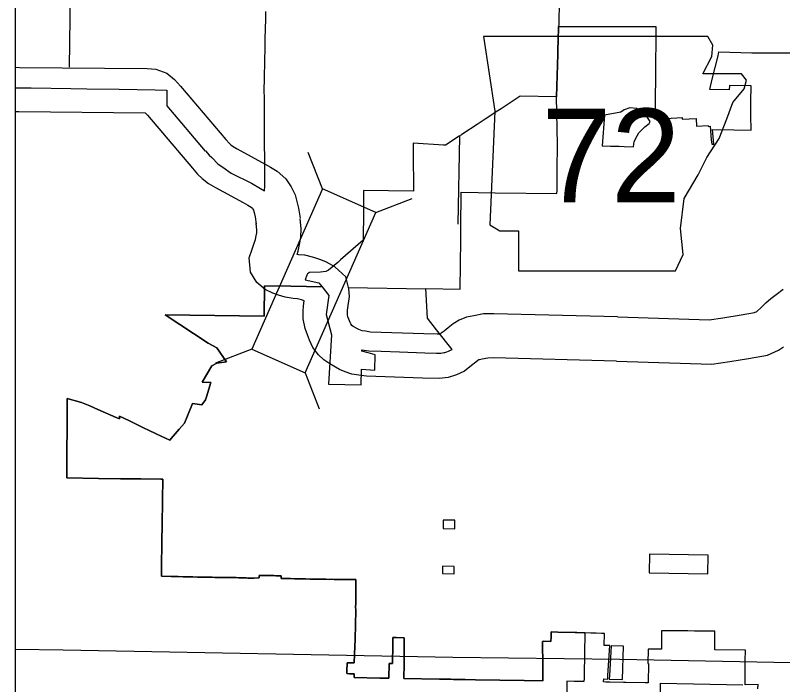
# Model space of a CAD drawing. Extents: x 309389.3 to 309420.2, y 336441.4 to 336461.2.
# Drawn here: x 309389.335 to 309390.124, y 336457.854 to 336458.542 of the extents above; entities that cross this region are included whole.
import ezdxf

# ---------------------------------------------------------------- set-up
doc = ezdxf.new("R2010")
doc.units = 0
for name, color, linetype in [('Level 24', 7, 'Continuous'), ('Level 37', 7, 'Continuous'), ('Level 4', 7, 'Continuous'), ('Level 62', 7, 'Continuous'), ('R_Contours', 7, 'Continuous'), ('R_MOT', 7, 'Continuous')]:
    doc.layers.add(name, color=color, linetype=linetype)

msp = doc.modelspace()

# ---------------------------------------------------------------- linework, layer by layer
at = {"layer": 'Level 24'}
for points in [[(309389.33514, 336458.48856), (309389.33946, 336458.48847), (309389.4708, 336458.48723), (309389.47977, 336458.48674), (309389.49099, 336458.48255), (309389.49889, 336458.47603), (309389.5051, 336458.46911), (309389.55175, 336458.41429), (309389.55535, 336458.41011), (309389.55665, 336458.40889), (309389.55919, 336458.40696), (309389.56328, 336458.40455), (309389.59207, 336458.38905), (309389.59749, 336458.3858), (309389.60453, 336458.38162), (309389.61336, 336458.37394), (309389.61896, 336458.36563), (309389.62294, 336458.35752), (309389.62479, 336458.35049), (309389.62651, 336458.34359), (309389.62794, 336458.33348)], [(309389.33514, 336458.4431), (309389.33878, 336458.44302), (309389.46854, 336458.4418), (309389.47088, 336458.43919), (309389.51722, 336458.38473), (309389.52246, 336458.37864), (309389.52725, 336458.37414), (309389.53384, 336458.36914), (309389.54098, 336458.36494), (309389.5696, 336458.34953), (309389.57421, 336458.34676), (309389.5778, 336458.34463), (309389.57901, 336458.34358), (309389.57952, 336458.34282), (309389.58014, 336458.34156), (309389.58076, 336458.3392), (309389.58184, 336458.33489), (309389.58293, 336458.32712)], [(309389.95453, 336458.23188), (309389.82708, 336458.23519), (309389.81643, 336458.23496), (309389.80665, 336458.23319), (309389.79914, 336458.23161), (309389.79164, 336458.22851), (309389.78544, 336458.22485), (309389.78023, 336458.22085), (309389.77599, 336458.21732), (309389.77313, 336458.21511), (309389.77231, 336458.21472), (309389.77088, 336458.21428), (309389.7691, 336458.21408), (309389.75507, 336458.21443), (309389.70049, 336458.21628), (309389.69516, 336458.21713), (309389.69192, 336458.21758), (309389.69025, 336458.21817), (309389.68838, 336458.21891), (309389.68264, 336458.2222), (309389.68132, 336458.22309), (309389.68117, 336458.22324), (309389.68001, 336458.22475), (309389.67933, 336458.22615), (309389.67804, 336458.2295), (309389.67711, 336458.23202), (309389.67673, 336458.23415), (309389.67672, 336458.23634), (309389.6769, 336458.23889), (309389.67875, 336458.25279), (309389.67805, 336458.26085), (309389.67485, 336458.27301), (309389.66381, 336458.28359), (309389.65513, 336458.28815), (309389.64932, 336458.29071), (309389.642, 336458.29312), (309389.6327, 336458.29541), (309389.62648, 336458.29591), (309389.62485, 336458.2962), (309389.62591, 336458.29952), (309389.62745, 336458.30622), (309389.62869, 336458.31342), (309389.62911, 336458.32279), (309389.62803, 336458.33274)], [(309389.95335, 336458.18644), (309389.82699, 336458.18973), (309389.82101, 336458.18959), (309389.81538, 336458.18857), (309389.81262, 336458.18799), (309389.81197, 336458.18773), (309389.81093, 336458.18711), (309389.80861, 336458.18533), (309389.80441, 336458.18184), (309389.79702, 336458.17613), (309389.7888, 336458.17224), (309389.78026, 336458.16961), (309389.77115, 336458.16856), (309389.75374, 336458.16899), (309389.69613, 336458.17095), (309389.68845, 336458.17217), (309389.6811, 336458.17319), (309389.67429, 336458.1756), (309389.6686, 336458.17786), (309389.65858, 336458.1836), (309389.65231, 336458.18783), (309389.647, 336458.19312), (309389.64117, 336458.20067), (309389.63759, 336458.20804), (309389.63551, 336458.21347), (309389.63308, 336458.22003), (309389.63129, 336458.23002), (309389.63126, 336458.23783), (309389.63165, 336458.24347), (309389.63232, 336458.24845), (309389.62942, 336458.24941), (309389.62541, 336458.2504), (309389.62073, 336458.25077), (309389.61246, 336458.25222), (309389.60577, 336458.25423), (309389.59985, 336458.25626), (309389.59209, 336458.26025), (309389.58358, 336458.2673), (309389.57714, 336458.27796), (309389.57561, 336458.29264), (309389.57875, 336458.30156), (309389.58044, 336458.30657), (309389.58204, 336458.31156), (309389.58287, 336458.31518), (309389.58341, 336458.3183), (309389.58354, 336458.32135), (309389.58284, 336458.32786)], [(309389.95462, 336458.23188), (309390.04875, 336458.22904), (309390.06287, 336458.2311), (309390.08151, 336458.2342), (309390.09536, 336458.23654), (309390.09784, 336458.23766), (309390.09854, 336458.23825), (309390.10136, 336458.2411), (309390.10682, 336458.24647), (309390.11209, 336458.25103), (309390.11766, 336458.25514), (309390.12472, 336458.26047)], [(309389.95325, 336458.18645), (309390.05135, 336458.18349), (309390.06988, 336458.18618), (309390.08903, 336458.18937), (309390.10874, 336458.1927), (309390.11983, 336458.19772), (309390.12497, 336458.2011)], [(309389.95668, 336457.87989), (309389.78498, 336457.88189), (309389.38426, 336457.88925), (309389.33514, 336457.89017)], [(309390.73336, 336457.86577), (309390.58465, 336457.86645), (309390.18588, 336457.87537), (309389.95686, 336457.87988)]]:
    msp.add_lwpolyline(points, dxfattribs=at)
at = {"layer": 'Level 37'}
for p, q in [((309389.65088, 336458.36354), (309389.63641, 336458.40083)), ((309389.70578, 336458.33934), (309389.74307, 336458.35381)), ((309389.57828, 336458.19883), (309389.54099, 336458.18436)), ((309389.63318, 336458.17463), (309389.64765, 336458.13734))]:
    msp.add_line(p, q, dxfattribs=at)
msp.add_lwpolyline([(309389.63318, 336458.17463), (309389.70578, 336458.33934), (309389.65088, 336458.36354), (309389.57828, 336458.19883)], close=True, dxfattribs=at)
at = {"layer": 'Level 4'}
for points in [[(309389.3909, 336458.48864), (309389.39318, 336458.66533), (309389.3932, 336458.66655)], [(309389.79193, 336458.41787), (309389.79031, 336458.32724)], [(309389.75737, 336458.26031), (309389.67727, 336458.26172)]]:
    msp.add_lwpolyline(points, dxfattribs=at)
at = {"layer": 'Level 62'}
for points in [[(309389.89457, 336458.5567), (309389.89391, 336458.53278), (309389.89384, 336458.53045)], [(309389.33514, 336458.46749), (309389.34942, 336458.46731), (309389.35135, 336458.46729), (309389.3922, 336458.46679), (309389.40867, 336458.4665), (309389.44177, 336458.4659), (309389.47878, 336458.46523), (309389.49097, 336458.46501), (309389.49093, 336458.45832), (309389.49088, 336458.44875), (309389.53028, 336458.40237), (309389.53057, 336458.40261), (309389.53443, 336458.39813), (309389.53714, 336458.39571), (309389.54385, 336458.38897), (309389.54866, 336458.38583), (309389.55725, 336458.37982), (309389.57801, 336458.36936), (309389.58715, 336458.36407), (309389.59128, 336458.36154), (309389.5918, 336458.36633), (309389.59163, 336458.39375), (309389.59152, 336458.41045), (309389.5915, 336458.41429), (309389.59138, 336458.43265), (309389.59131, 336458.44463), (309389.59124, 336458.45569), (309389.59122, 336458.45857), (309389.59119, 336458.46315), (309389.59148, 336458.47873), (309389.59176, 336458.49365), (309389.59209, 336458.51031), (309389.59216, 336458.51409), (309389.59223, 336458.51767), (309389.59262, 336458.53789), (309389.59277, 336458.54578)], [(309389.89384, 336458.53045), (309389.89342, 336458.51547), (309389.8932, 336458.5076), (309389.89305, 336458.502), (309389.89183, 336458.45829), (309389.8544, 336458.45878), (309389.83487, 336458.44599), (309389.83122, 336458.4436), (309389.81834, 336458.43517), (309389.81016, 336458.42981), (309389.79536, 336458.42012), (309389.79399, 336458.41923), (309389.79163, 336458.41768), (309389.77762, 336458.40851), (309389.77538, 336458.40865), (309389.74436, 336458.41048), (309389.74439, 336458.40168), (309389.74448, 336458.36106), (309389.69334, 336458.36197), (309389.69319, 336458.34071), (309389.69297, 336458.31091), (309389.66952, 336458.29051), (309389.66668, 336458.28804), (309389.65724, 336458.27983), (309389.65432, 336458.27875), (309389.64893, 336458.27795), (309389.63773, 336458.2775), (309389.63569, 336458.27638), (309389.63506, 336458.27472), (309389.63331, 336458.27017), (309389.63335, 336458.27016), (309389.64718, 336458.26709), (309389.65069, 336458.26294), (309389.61845, 336458.26342), (309389.59142, 336458.26383), (309389.59095, 336458.23275), (309389.48936, 336458.23412), (309389.53337, 336458.20479), (309389.54234, 336458.20007), (309389.5522, 336458.1857), (309389.54221, 336458.18432), (309389.53727, 336458.18183), (309389.52733, 336458.16474), (309389.53628, 336458.1646), (309389.53161, 336458.14995), (309389.53062, 336458.14683), (309389.52685, 336458.14149), (309389.51738, 336458.14296), (309389.51669, 336458.14133), (309389.51206, 336458.13027), (309389.50895, 336458.12286), (309389.50356, 336458.11671), (309389.49538, 336458.107), (309389.49395, 336458.10533), (309389.48048, 336458.11149), (309389.47707, 336458.11314), (309389.47494, 336458.11417), (309389.46502, 336458.11898), (309389.4524, 336458.12509), (309389.44213, 336458.13006), (309389.44224, 336458.12711), (309389.43871, 336458.12869), (309389.41998, 336458.13685), (309389.41634, 336458.13841), (309389.41538, 336458.13882), (309389.41167, 336458.14041), (309389.40306, 336458.14398), (309389.38853, 336458.14807), (309389.38835, 336458.11827), (309389.3882, 336458.09334), (309389.38804, 336458.06641), (309389.42069, 336458.06598), (309389.44338, 336458.06567), (309389.46429, 336458.06539), (309389.48469, 336458.06511), (309389.4868, 336458.06508), (309389.48668, 336458.05696), (309389.4866, 336458.05216), (309389.48653, 336458.04737), (309389.48646, 336458.04258), (309389.48639, 336458.03784), (309389.48631, 336458.03305), (309389.48624, 336458.02824), (309389.48617, 336458.02346), (309389.4861, 336458.01869), (309389.48605, 336458.01543), (309389.48602, 336458.01395), (309389.48597, 336458.01039), (309389.48595, 336458.00916), (309389.48588, 336458.00441), (309389.48581, 336457.9996), (309389.48573, 336457.99478), (309389.48566, 336457.99001), (309389.48559, 336457.98525), (309389.48552, 336457.98072), (309389.48549, 336457.97855), (309389.48539, 336457.97246), (309389.48533, 336457.96546), (309389.49551, 336457.9652), (309389.50255, 336457.96503)], [(309389.89251, 336458.39023), (309389.89263, 336458.40189), (309389.89271, 336458.40919), (309389.89183, 336458.45829), (309389.89305, 336458.502), (309389.8932, 336458.5076), (309389.89342, 336458.51547), (309389.89384, 336458.53045), (309389.91649, 336458.53048), (309389.93203, 336458.53052), (309389.994, 336458.53058), (309389.99369, 336458.50607), (309389.99364, 336458.50209), (309389.99353, 336458.49309), (309389.99334, 336458.47786), (309389.99308, 336458.45679), (309389.99298, 336458.44622), (309389.99296, 336458.44463), (309389.99287, 336458.43511), (309390.02086, 336458.43701), (309390.02098, 336458.43512), (309390.03523, 336458.43606), (309390.03573, 336458.4279), (309390.04779, 336458.42871), (309390.04787, 336458.42781), (309390.04966, 336458.42793), (309390.05091, 336458.41395), (309390.05129, 336458.40966), (309390.0535, 336458.40966), (309390.05225, 336458.42449), (309390.0742, 336458.4241), (309390.09185, 336458.42379), (309390.09162, 336458.43897), (309390.09139, 336458.45347), (309390.09176, 336458.46939), (309390.06952, 336458.46978), (309390.06908, 336458.46536), (309390.0493, 336458.46587), (309390.05182, 336458.47622), (309390.05777, 336458.50038), (309390.05862, 336458.50438), (309390.09257, 336458.50346), (309390.11997, 336458.50331), (309390.14346, 336458.50322)], [(309389.48588, 336458.00441), (309389.48595, 336458.00916), (309389.48597, 336458.01039), (309389.48602, 336458.01395), (309389.48605, 336458.01543), (309389.4861, 336458.01869), (309389.48617, 336458.02346), (309389.48624, 336458.02824), (309389.48631, 336458.03305), (309389.48639, 336458.03784), (309389.48646, 336458.04258), (309389.48653, 336458.04737), (309389.4866, 336458.05216), (309389.48668, 336458.05696), (309389.4868, 336458.06508), (309389.48469, 336458.06511), (309389.46429, 336458.06539), (309389.44338, 336458.06567), (309389.42069, 336458.06598), (309389.38804, 336458.06641), (309389.3882, 336458.09334), (309389.38835, 336458.11827), (309389.38853, 336458.14807), (309389.40306, 336458.14398), (309389.41167, 336458.14041), (309389.41538, 336458.13882), (309389.41634, 336458.13841), (309389.41998, 336458.13685), (309389.43871, 336458.12869), (309389.44224, 336458.12711), (309389.44213, 336458.13006), (309389.4524, 336458.12509), (309389.46502, 336458.11898), (309389.47494, 336458.11417), (309389.47707, 336458.11314), (309389.48048, 336458.11149), (309389.49395, 336458.10533), (309389.49538, 336458.107), (309389.50356, 336458.11671), (309389.50895, 336458.12286), (309389.51206, 336458.13027), (309389.51669, 336458.14133), (309389.51738, 336458.14296), (309389.52685, 336458.14149), (309389.53062, 336458.14683), (309389.53161, 336458.14995), (309389.53628, 336458.1646), (309389.52733, 336458.16474), (309389.53727, 336458.18183), (309389.54221, 336458.18432), (309389.5522, 336458.1857), (309389.54234, 336458.20007), (309389.53337, 336458.20479), (309389.48936, 336458.23412), (309389.59095, 336458.23275), (309389.59142, 336458.26383), (309389.61845, 336458.26342), (309389.65069, 336458.26294), (309389.65765, 336458.25387), (309389.65488, 336458.23447), (309389.66042, 336458.21345), (309389.6571, 336458.16278), (309389.69074, 336458.16227), (309389.69104, 336458.17817), (309389.70479, 336458.17728), (309389.70534, 336458.19281), (309389.69784, 336458.19486), (309389.69139, 336458.19662), (309389.69142, 336458.19824), (309389.69876, 336458.19723), (309389.71128, 336458.19676), (309389.73037, 336458.196), (309389.75612, 336458.19503), (309389.76839, 336458.19457), (309389.76926, 336458.19455), (309389.77037, 336458.19456), (309389.77153, 336458.19462), (309389.77286, 336458.19474), (309389.77431, 336458.19494), (309389.77573, 336458.19521), (309389.77688, 336458.19548), (309389.77889, 336458.19607), (309389.78076, 336458.19676), (309389.78267, 336458.19763), (309389.78433, 336458.19851), (309389.78436, 336458.19853), (309389.76841, 336458.21877), (309389.75913, 336458.23055), (309389.75732, 336458.26117), (309389.79277, 336458.26056), (309389.79321, 336458.3112), (309389.79331, 336458.32355), (309389.79363, 336458.36018), (309389.82843, 336458.35965), (309389.89216, 336458.35869), (309389.8922, 336458.36182), (309389.89229, 336458.36977), (309389.89236, 336458.37659), (309389.89243, 336458.38341), (309389.89251, 336458.39023)], [(309389.68373, 336457.86127), (309389.68375, 336457.86508), (309389.68375, 336457.86515), (309389.67867, 336457.86523), (309389.67604, 336457.86528), (309389.67611, 336457.86796), (309389.67633, 336457.8763), (309389.68369, 336457.87633), (309389.6843, 336457.89348), (309389.68446, 336457.89987), (309389.68461, 336457.9028), (309389.68471, 336457.90543), (309389.68492, 336457.91098), (309389.68513, 336457.91649), (309389.68513, 336457.92182), (309389.68514, 336457.92407), (309389.68515, 336457.92723), (309389.68514, 336457.93165), (309389.68513, 336457.93285), (309389.68516, 336457.93806), (309389.68515, 336457.93922), (309389.68514, 336457.94367), (309389.68515, 336457.94681), (309389.68516, 336457.94915), (309389.68514, 336457.95439), (309389.68516, 336457.95691), (309389.68514, 336457.96193), (309389.68286, 336457.96197), (309389.67791, 336457.96203), (309389.67672, 336457.96206), (309389.67302, 336457.9621), (309389.67052, 336457.96208), (309389.66802, 336457.96211), (309389.66516, 336457.96215), (309389.66313, 336457.9622), (309389.65981, 336457.96221), (309389.6583, 336457.96213), (309389.65444, 336457.96226), (309389.65329, 336457.96226), (309389.6491, 336457.96234), (309389.64846, 336457.96236), (309389.64373, 336457.96245), (309389.64352, 336457.96245), (309389.6386, 336457.96255), (309389.63836, 336457.96255), (309389.63367, 336457.96264), (309389.63301, 336457.96265), (309389.6286, 336457.96274), (309389.62763, 336457.96276), (309389.62335, 336457.96284), (309389.62228, 336457.96286), (309389.61808, 336457.96294), (309389.61691, 336457.96296), (309389.61314, 336457.96303), (309389.61153, 336457.96307), (309389.60844, 336457.96313), (309389.60844, 336457.96589), (309389.60622, 336457.96592), (309389.60292, 336457.96596), (309389.60085, 336457.96598), (309389.5979, 336457.96601), (309389.5934, 336457.96606), (309389.59119, 336457.9661), (309389.58575, 336457.96618), (309389.58575, 336457.96361), (309389.58082, 336457.96354), (309389.57438, 336457.96357), (309389.57235, 336457.96368), (309389.57072, 336457.96373), (309389.56734, 336457.96384), (309389.56465, 336457.96389), (309389.56233, 336457.96394), (309389.55887, 336457.96402), (309389.55736, 336457.96401), (309389.55253, 336457.96399), (309389.54746, 336457.96413), (309389.54649, 336457.96415), (309389.54245, 336457.96421), (309389.54045, 336457.96423), (309389.53747, 336457.96431), (309389.53438, 336457.96439), (309389.53243, 336457.96442), (309389.52775, 336457.9645), (309389.52742, 336457.96449), (309389.52513, 336457.96445), (309389.52252, 336457.96452), (309389.51763, 336457.96464), (309389.5125, 336457.96477), (309389.50757, 336457.9649), (309389.50255, 336457.96503), (309389.49551, 336457.9652), (309389.48533, 336457.96546), (309389.48539, 336457.97246), (309389.48549, 336457.97855), (309389.48552, 336457.98072), (309389.48559, 336457.98525), (309389.48566, 336457.99001), (309389.48573, 336457.99478), (309389.48581, 336457.9996), (309389.48588, 336458.00441)], [(309389.50255, 336457.96503), (309389.50757, 336457.9649), (309389.5125, 336457.96477), (309389.51763, 336457.96464), (309389.52252, 336457.96452), (309389.52513, 336457.96445), (309389.52742, 336457.96449), (309389.52775, 336457.9645), (309389.53243, 336457.96442), (309389.53438, 336457.96439), (309389.53747, 336457.96431), (309389.54045, 336457.96423), (309389.54245, 336457.96421), (309389.54649, 336457.96415), (309389.54746, 336457.96413), (309389.55253, 336457.96399), (309389.55736, 336457.96401), (309389.55887, 336457.96402), (309389.56233, 336457.96394), (309389.56465, 336457.96389), (309389.56734, 336457.96384), (309389.57072, 336457.96373), (309389.57235, 336457.96368), (309389.57438, 336457.96357), (309389.58082, 336457.96354), (309389.58575, 336457.96361), (309389.58575, 336457.96618), (309389.59119, 336457.9661), (309389.5934, 336457.96606), (309389.5979, 336457.96601), (309389.60085, 336457.96598), (309389.60292, 336457.96596), (309389.60622, 336457.96592), (309389.60844, 336457.96589), (309389.60844, 336457.96313), (309389.61153, 336457.96307), (309389.61314, 336457.96303), (309389.61691, 336457.96296), (309389.61808, 336457.96294), (309389.62228, 336457.96286), (309389.62335, 336457.96284), (309389.62763, 336457.96276), (309389.6286, 336457.96274), (309389.63301, 336457.96265), (309389.63367, 336457.96264), (309389.63836, 336457.96255), (309389.6386, 336457.96255), (309389.64352, 336457.96245), (309389.64373, 336457.96245), (309389.64846, 336457.96236), (309389.6491, 336457.96234), (309389.65329, 336457.96226), (309389.65444, 336457.96226), (309389.6583, 336457.96213), (309389.65981, 336457.96221), (309389.66313, 336457.9622), (309389.66516, 336457.96215), (309389.66802, 336457.96211), (309389.67052, 336457.96208), (309389.67302, 336457.9621), (309389.67672, 336457.96206), (309389.67791, 336457.96203), (309389.68286, 336457.96197), (309389.68514, 336457.96193), (309389.68516, 336457.95691), (309389.68514, 336457.95439), (309389.68516, 336457.94915), (309389.68515, 336457.94681), (309389.68514, 336457.94367), (309389.68515, 336457.93922), (309389.68516, 336457.93806), (309389.68513, 336457.93285), (309389.68514, 336457.93165), (309389.68515, 336457.92723), (309389.68514, 336457.92407), (309389.68513, 336457.92182), (309389.68513, 336457.91649), (309389.68492, 336457.91098), (309389.68471, 336457.90543), (309389.68461, 336457.9028), (309389.68446, 336457.89987), (309389.6843, 336457.89348), (309389.68369, 336457.87633), (309389.67633, 336457.8763), (309389.67611, 336457.86796), (309389.67604, 336457.86528), (309389.67867, 336457.86523), (309389.68375, 336457.86515), (309389.68375, 336457.86508), (309389.68373, 336457.86127), (309389.70994, 336457.86078), (309389.71936, 336457.86061), (309389.71943, 336457.87559), (309389.72314, 336457.87553), (309389.72317, 336457.88148), (309389.72323, 336457.88906), (309389.72334, 336457.90231), (309389.7267, 336457.90229), (309389.72672, 336457.90229), (309389.73428, 336457.90212)], [(309390.09888, 336457.8496), (309390.09895, 336457.85415), (309390.08576, 336457.85378), (309390.0858, 336457.85741), (309390.08581, 336457.85794), (309390.08585, 336457.86093), (309390.0857, 336457.87855), (309390.08594, 336457.88923), (309390.05465, 336457.88969), (309390.05459, 336457.90889), (309390.05028, 336457.90893), (309390.04475, 336457.90897), (309390.0415, 336457.909), (309390.03922, 336457.90901), (309390.03369, 336457.90906), (309390.02683, 336457.90911), (309390.02368, 336457.90915), (309390.01178, 336457.90923), (309389.99975, 336457.90923), (309389.99954, 336457.89034), (309389.99017, 336457.89041), (309389.98668, 336457.89044), (309389.98597, 336457.89045), (309389.9857, 336457.87579), (309389.98641, 336457.87577), (309389.98603, 336457.85574), (309389.98281, 336457.85582), (309389.96314, 336457.85623), (309389.96236, 336457.85624), (309389.9605, 336457.85628), (309389.94664, 336457.85656), (309389.94488, 336457.8566), (309389.94249, 336457.85665), (309389.94007, 336457.8567), (309389.94021, 336457.85982), (309389.94442, 336457.85962), (309389.94463, 336457.86347), (309389.94636, 336457.89405), (309389.94071, 336457.89425), (309389.94104, 336457.9066), (309389.94064, 336457.90661), (309389.93782, 336457.90669), (309389.93233, 336457.90686), (309389.93072, 336457.90691), (309389.92684, 336457.90702), (309389.92079, 336457.9072), (309389.9203, 336457.90721), (309389.91273, 336457.90743), (309389.91077, 336457.90749), (309389.89297, 336457.90805), (309389.88628, 336457.90826), (309389.8861, 336457.90326), (309389.88601, 336457.89848), (309389.87868, 336457.89859), (309389.87738, 336457.89843), (309389.87735, 336457.89237), (309389.87736, 336457.89161), (309389.87746, 336457.87986), (309389.87767, 336457.85791), (309389.85826, 336457.85822), (309389.8084, 336457.85903), (309389.79781, 336457.8592), (309389.7858, 336457.8594), (309389.78308, 336457.85944), (309389.7715, 336457.85965), (309389.73479, 336457.86032), (309389.73486, 336457.87537), (309389.7349, 336457.88042), (309389.7349, 336457.88042), (309389.73495, 336457.88854), (309389.73495, 336457.88878), (309389.735, 336457.89492), (309389.73506, 336457.9021), (309389.73428, 336457.90212), (309389.72672, 336457.90229), (309389.7267, 336457.90229), (309389.72334, 336457.90231), (309389.72323, 336457.88906), (309389.72317, 336457.88148), (309389.72314, 336457.87553), (309389.71943, 336457.87559), (309389.71936, 336457.86061), (309389.70994, 336457.86078), (309389.68373, 336457.86127)], [(309389.73428, 336457.90212), (309389.73506, 336457.9021), (309389.735, 336457.89492), (309389.73495, 336457.88878), (309389.73495, 336457.88854), (309389.7349, 336457.88042), (309389.7349, 336457.88042), (309389.73486, 336457.87537), (309389.73479, 336457.86032), (309389.7715, 336457.85965), (309389.78308, 336457.85944), (309389.7858, 336457.8594), (309389.79781, 336457.8592), (309389.8084, 336457.85903), (309389.85826, 336457.85822), (309389.87767, 336457.85791), (309389.87746, 336457.87986), (309389.87736, 336457.89161), (309389.87735, 336457.89237), (309389.87738, 336457.89843), (309389.87868, 336457.89859), (309389.88601, 336457.89848), (309389.8861, 336457.90326), (309389.88628, 336457.90826), (309389.89297, 336457.90805), (309389.91077, 336457.90749), (309389.91273, 336457.90743), (309389.9203, 336457.90721), (309389.92079, 336457.9072), (309389.92003, 336457.86403), (309389.91996, 336457.86022), (309389.91991, 336457.85711), (309389.90987, 336457.85732), (309389.90217, 336457.85748), (309389.90198, 336457.83135)], [(309389.9986, 336457.80763), (309389.99869, 336457.85549), (309390.08315, 336457.85383)]]:
    msp.add_lwpolyline(points, dxfattribs=at)
for points in [[(309389.97094, 336458.4069), (309389.97161, 336458.41219), (309389.97457, 336458.4182), (309389.97619, 336458.4213), (309389.9787, 336458.42357), (309389.9824, 336458.4274), (309389.98688, 336458.43064), (309389.98807, 336458.43285), (309389.98206, 336458.44165), (309389.97444, 336458.44616), (309389.96698, 336458.44684), (309389.9614, 336458.44484), (309389.95771, 336458.44233), (309389.94088, 336458.43918), (309389.93858, 336458.40784), (309389.94737, 336458.40759), (309389.95614, 336458.40733), (309389.96117, 336458.40718)], [(309389.787, 336458.0141), (309389.78705, 336458.01831), (309389.78711, 336458.02287), (309389.77516, 336458.0231), (309389.77513, 336458.02134), (309389.77509, 336458.01853), (309389.77502, 336458.01435)], [(309390.04719, 336457.96801), (309390.04769, 336457.98698), (309389.98723, 336457.988), (309389.98698, 336457.96892)], [(309389.78641, 336457.96774), (309389.78648, 336457.97319), (309389.78651, 336457.9754), (309389.77443, 336457.97566), (309389.77432, 336457.9685), (309389.77431, 336457.96806)], [(309389.95972, 336457.85933), (309389.9607, 336457.89352), (309389.94787, 336457.89399), (309389.94615, 336457.86343), (309389.94593, 336457.85964)]]:
    msp.add_lwpolyline(points, close=True, dxfattribs=at)
at = {"layer": 'R_Contours'}
msp.add_lwpolyline([(309389.81677, 336458.52027), (309389.82831, 336458.44337), (309389.82318, 336458.32674), (309389.83343, 336458.32034), (309389.85266, 336458.32034), (309389.85266, 336458.27932), (309390.01415, 336458.27932), (309390.02184, 336458.29598), (309390.01927, 336458.3229), (309390.02312, 336458.35366), (309390.03722, 336458.37801), (309390.04619, 336458.39595), (309390.05901, 336458.41518), (309390.0667, 336458.43568), (309390.0731, 336458.45235), (309390.08464, 336458.46644), (309390.0872, 336458.47542), (309390.08207, 336458.48182), (309390.04234, 336458.48182), (309390.05132, 336458.49977), (309390.0526, 336458.5113), (309390.04728, 336458.52016)], close=True, dxfattribs=at)
at = {"layer": 'R_MOT'}
msp.add_lwpolyline([(309389.33514, 336459.8498), (309394.8545, 336459.8498), (309394.8545, 336455.36964), (309389.33514, 336455.36964)], close=True, dxfattribs=at)

# ---------------------------------------------------------------- texts
at = {"layer": 'R_Contours'}
msp.add_text('72', height=0.096, dxfattribs=at).set_placement((309389.87645, 336458.34988))

doc.saveas('drawing.dxf')
